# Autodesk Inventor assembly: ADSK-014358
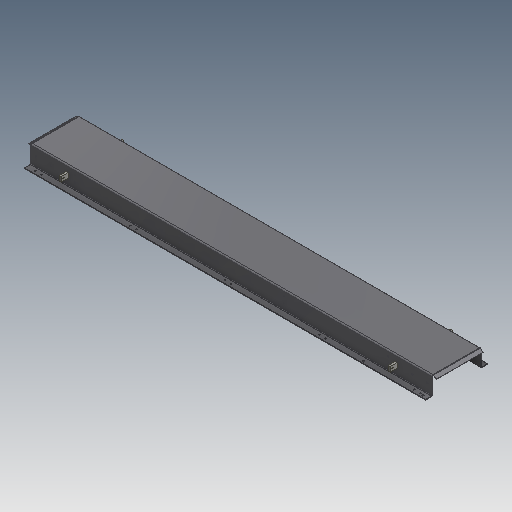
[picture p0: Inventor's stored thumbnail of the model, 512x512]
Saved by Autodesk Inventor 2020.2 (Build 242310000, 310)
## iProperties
Created: 2000-01
Part Number: ADSK-014358
Document SubType Name: Assembly
Designer: cmcgourin
Mass: 3239.21 g
Surface Area: 20150.1 cm^2
Volume: 3009.64 cm^3
Density: 1.07628 g/cm^3
Control State: 0
Checked Out: False
Master: False
Shininess: 0.0
Length Units: 11269
Angle Units: 11279
Time Units: 11290
Mass Units: 11283
Length Display Precision: 3
Angle Display Precision: 2
Compacted: True
Dimensions: 2068,6x92x318 mm
Mass: 3,239 kg
DocNumber: ADSK-014358
Folder: 01 - Themengebiete\Simplification\01 - Packaging machine\
Original: C:\AB_Vault\CAD\01 - Themengebiete\Simplification\01 - Packaging machine\500467R.iam
VDS_Category: 3D Komponenten
VDS_NumSchm: Autodesk
Density: 0.0
Volumn: 0.0
Area: 0.0
PropertySet Name: Model Information
Author: cmcgourin
Revision Number: -
Title: 500467R
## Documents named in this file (3)
- D:\07 - DEMODATEN\OTX 2019 - Dataset - UPDATE - Dez2019\Designs\07-Packing machine\ADSK-014358.iam
- D:\07 - DEMODATEN\OTX 2019 - Dataset - UPDATE - Dez2019\Designs\07-Packing machine\Parts\ADSK-011413.ipt
- D:\07 - DEMODATEN\OTX 2019 - Dataset - UPDATE - Dez2019\Designs\07-Packing machine\Parts\ADSK-014359.ipt
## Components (5 placed, 2 different names)
1. ADSK-011413:1 — Passend:1, Passend:3, Fluchtend:1, Fluchtend:2, Fluchtend:3, Fluchtend:4, Passend:6, Fluchtend:5
2. ADSK-011413:2 — Passend:4, Fluchtend:4, Passend:7
3. ADSK-011413:3 — Passend:2, Fluchtend:3, Passend:6
4. ADSK-011413:4 — Passend:5, Fluchtend:2, Passend:7, Fluchtend:5, Fluchtend:6
5. ADSK-014359:1 — Passend:1, Passend:2, Passend:3, Passend:4, Passend:5, Fluchtend:1
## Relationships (13: Mate 7, Flush 6)
- Passend:1 [Mate]: ADSK-011413:1 ↔ ADSK-014359:1
- Passend:2 [Mate]: ADSK-011413:3 ↔ ADSK-014359:1
- Passend:3 [Mate]: ADSK-011413:1 ↔ ADSK-014359:1
- Passend:4 [Mate]: ADSK-011413:2 ↔ ADSK-014359:1
- Passend:5 [Mate]: ADSK-011413:4 ↔ ADSK-014359:1
- Fluchtend:1 [Flush]: ADSK-011413:1 ↔ ADSK-014359:1
- Fluchtend:2 [Flush]: ADSK-011413:1 ↔ ADSK-011413:4
- Fluchtend:3 [Flush]: ADSK-011413:1 ↔ ADSK-011413:3
- Fluchtend:4 [Flush]: ADSK-011413:1 ↔ ADSK-011413:2
- Passend:6 [Mate]: ADSK-011413:1 ↔ ADSK-011413:3
- Passend:7 [Mate]: ADSK-011413:2 ↔ ADSK-011413:4
- Fluchtend:5 [Flush]: ADSK-011413:1 ↔ ADSK-011413:4
- Fluchtend:6 [Flush]: ADSK-011413:4
